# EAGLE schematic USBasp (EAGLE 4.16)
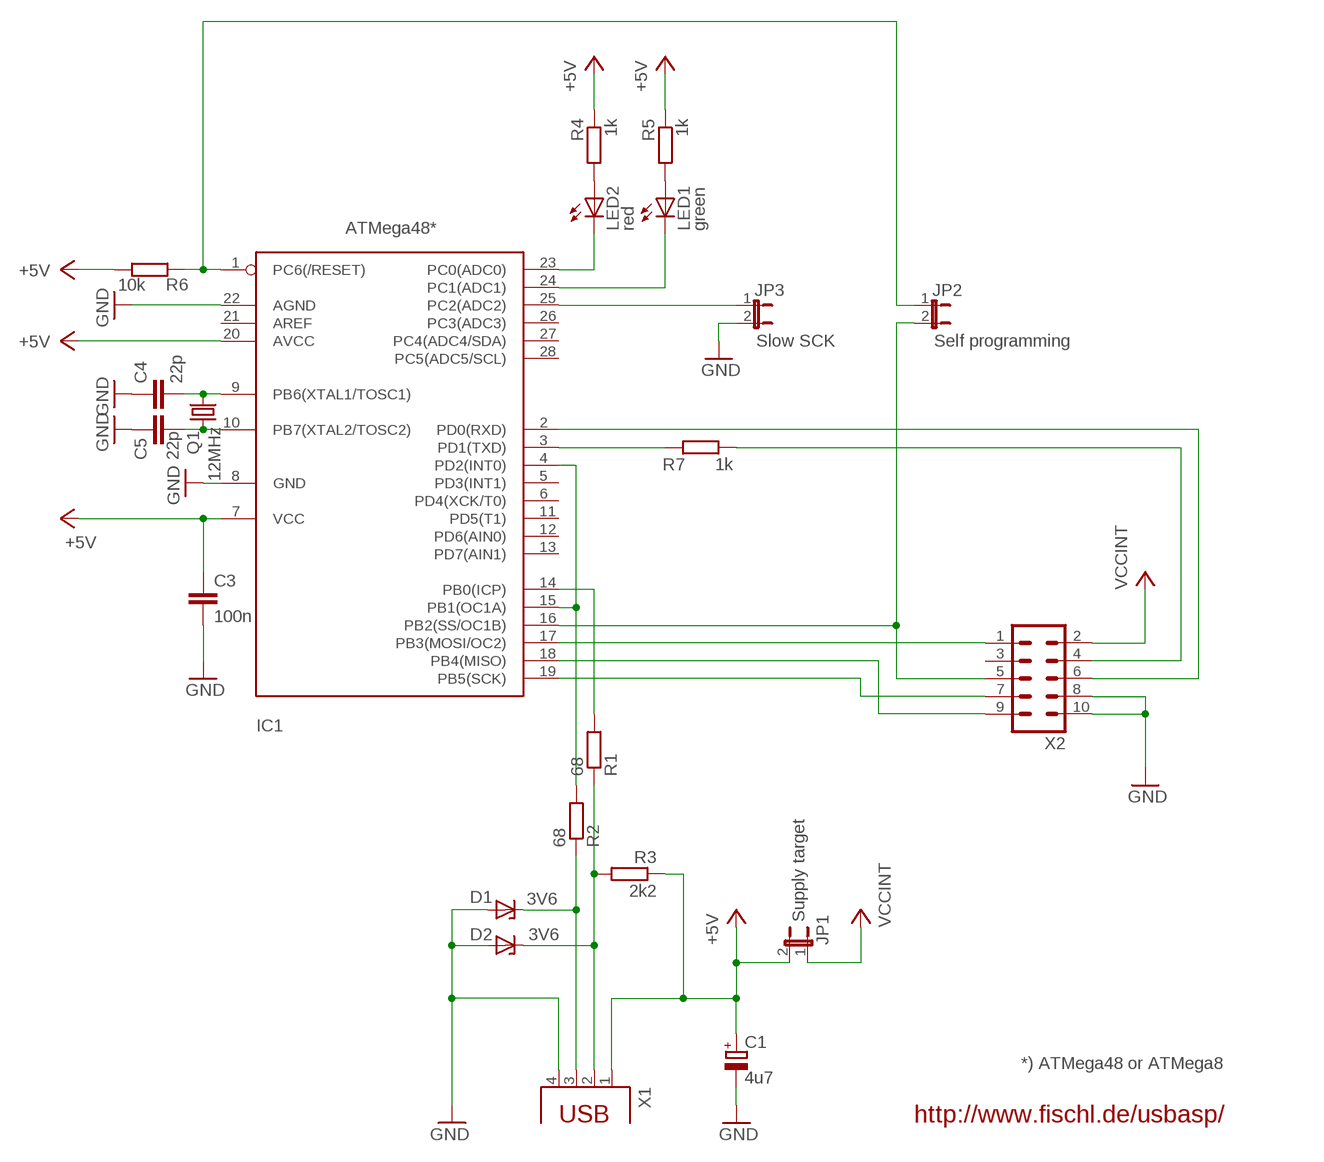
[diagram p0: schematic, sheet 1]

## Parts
C1  4u7  CPOL-EUE2.5-5  [E2,5-5]
C3  100n  C-EU025-024X044  [C025-024X044]
C4  22p  C-EU025-024X044  [C025-024X044]
C5  22p  C-EU025-024X044  [C025-024X044]
D1  3V6  ZENER-DIODEDO34-7  [DO34Z7]
D2  3V6  ZENER-DIODEDO34-7  [DO34Z7]
IC1  ATMega48*  MEGA8-P  [DIL28-3]
JP1  Supply target  JP1E  [JP1]
JP2  Self programming  JP1E  [JP1]
JP3  Slow SCK  JP1E  [JP1]
LED1  green  LED3MM  [LED3MM]
LED2  red  LED3MM  [LED3MM]
Q1  12MHz  CRYTALHC49S  [HC49/S]
R1  68  R-EU_0207/10  [0207/10]
R2  68  R-EU_0207/10  [0207/10]
R3  2k2  R-EU_0207/10  [0207/10]
R4  1k  R-EU_0207/10  [0207/10]
R5  1k  R-EU_0207/10  [0207/10]
R6  10k  R-EU_0207/10  [0207/10]
R7  1k  R-EU_0207/10  [0207/10]
X1  PN61729  [PN61729]
X2  ML10L  [ML10L]

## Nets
+5V: C1.+ C3.1 IC1.7(VCC) IC1.20(AVCC) JP1.2 R3.1 R4.1 R5.1 R6.1 X1.1
GND: C1.- C3.2 C4.1 C5.1 D1.A D2.A IC1.8(GND) IC1.22(AGND) JP3.2 X1.4 X2.8 X2.10
N$1: IC1.1(PC6(/RESET)) JP2.1 R6.2
N$2: IC1.16(PB2(SS/OC1B)) JP2.2 X2.5
N$3: IC1.17(PB3(MOSI/OC2)) X2.1
N$4: IC1.19(PB5(SCK)) X2.7
N$5: D2.C R1.1 R3.2 X1.2
N$6: IC1.18(PB4(MISO)) X2.9
N$7: IC1.4(PD2(INT0)) IC1.15(PB1(OC1A)) R2.2
N$8: D1.C R2.1 X1.3
N$9: IC1.3(PD1(TXD)) R7.2
N$10: R7.1 X2.4
N$11: IC1.2(PD0(RXD)) X2.6
N$12: IC1.25(PC2(ADC2)) JP3.1
N$13: LED2.A R4.2
N$14: IC1.23(PC0(ADC0)) LED2.K(C)
N$15: IC1.24(PC1(ADC1)) LED1.K(C)
N$16: IC1.14(PB0(ICP)) R1.2
N$22: C4.2 IC1.9(PB6(XTAL1/TOSC1)) Q1.2
N$23: C5.2 IC1.10(PB7(XTAL2/TOSC2)) Q1.1
N$25: LED1.A R5.2
VCCINT: JP1.1 X2.2
Unconnected: IC1.5(PD3(INT1)) IC1.6(PD4(XCK/T0)) IC1.11(PD5(T1)) IC1.12(PD6(AIN0)) IC1.13(PD7(AIN1)) IC1.21(AREF) IC1.26(PC3(ADC3)) IC1.27(PC4(ADC4/SDA)) IC1.28(PC5(ADC5/SCL)) X2.3

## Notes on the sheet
- *) ATMega48 or ATMega8
- http://www.fischl.de/usbasp/

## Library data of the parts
C1 = rcl:CPOL-EU: POLARIZED CAPACITOR, European symbol
C3-C5 = rcl:C-EU: CAPACITOR, European symbol
D1 D2 = diode:ZENER-DIODE: Z-Diode
IC1 = atmel:MEGA8-P: MICROCONTROLLER 8 Kbytes FLASH 1 kbytes SRAM 512 bytes EEPROM USART 4-channel 10 bit ADC 2-channel 8 bit ADC Source: avr.lbr
JP1-JP3 = jumper:JP1E: JUMPER
LED1 LED2 = led:LED: LED
Q1 = crystal:CRYTAL: CRYSTAL
R1-R7 = rcl:R-EU_: RESISTOR, European symbol
X1 = con-berg:PN61729: BERG USB connector
X2 = con-harting-ml:ML10: HARTING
